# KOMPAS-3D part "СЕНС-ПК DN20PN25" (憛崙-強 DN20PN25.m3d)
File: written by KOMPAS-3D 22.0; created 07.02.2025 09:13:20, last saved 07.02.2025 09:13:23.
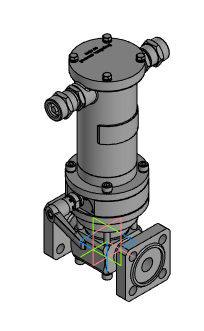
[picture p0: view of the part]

Document properties: Автор: setup; Полное имя файла: \\10.10.77.77\!! users\Савин А.Г\!Клапаны 3D для заказчика\СЕНС-ПК\1. СЕНС-ПК\СЕНС-ПК DN20PN25.m3d

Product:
- Body: Тело 3
    Масса: 9.898204
- Part/product: СЕНС-ПК DN20PN25
    Масса: 9.704967

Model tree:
1. Операция без истории:1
